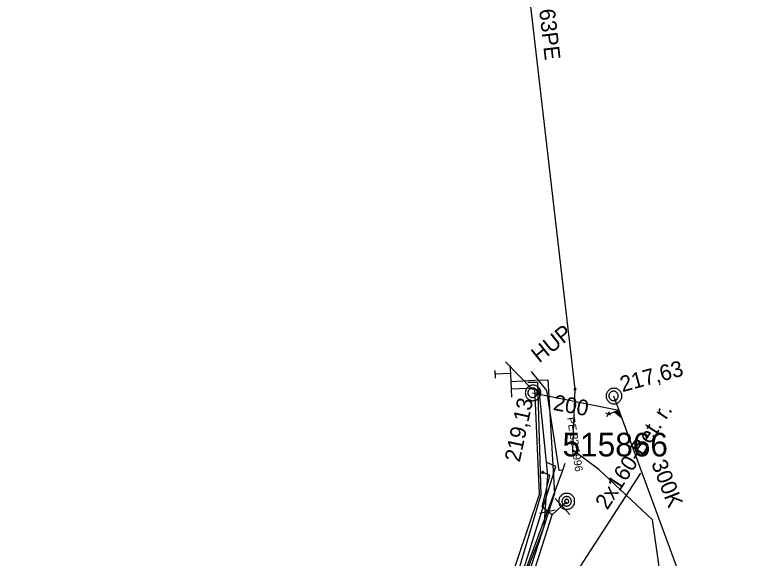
# Model space of a CAD drawing. Extents: x -746464 to -745690, y -1051581 to -1049993.
# Drawn here: x -746322.25 to -746275.6, y -1050804.49 to -1050769.98 of the extents above; entities that cross this region are included whole.
import ezdxf

# ---------------------------------------------------------------- set-up
doc = ezdxf.new("R2010")
doc.units = 0
for name, color, linetype in [('04_CETIN_sdelovaci_podzem', 7, 'Continuous'), ('45_Eltodo_popisy', 7, 'Continuous'), ('45_Eltodo_vedeni_NN_zemni', 7, 'Continuous'), ('48_Prazs_plynarenska_STL', 7, 'Continuous'), ('48_Prazs_plynarenska_STL_popisy', 7, 'Continuous'), ('51_PVaK_kanal_jednotna_neoverena poloha_pripojka', 7, 'Continuous'), ('51_PVaK_kanal_jednotna_overena poloha_rad', 7, 'Continuous'), ('51_PVaK_kanal_objekty', 7, 'Continuous'), ('51_PVaK_kanal_popisy', 7, 'Continuous'), ('51_PVaK_vodovod_chranicky_objekty', 7, 'Continuous'), ('51_PVaK_vodovod_NEPROVOZUJE PVK_neoverene poloha', 7, 'Continuous'), ('51_PVaK_vodovod_NEPROVOZUJE PVK_overena poloha', 7, 'Continuous'), ('51_PVaK_vodovod_overena poloha_pripojka', 7, 'Continuous'), ('51_PVaK_vodovod_overena poloha_rad', 7, 'Continuous'), ('51_PVaK_vodovod_popisy', 7, 'Continuous'), ('55_PREdi_NN', 7, 'Continuous'), ('55_PREdi_NN_pripojovaci_misto', 7, 'Continuous'), ('55_PREdi_stavby_popisy', 7, 'Continuous')]:
    doc.layers.add(name, color=color, linetype=linetype)

msp = doc.modelspace()

# ---------------------------------------------------------------- linework, layer by layer
at = {"layer": '04_CETIN_sdelovaci_podzem'}
for points in [[(-746289.39, -1050793.76), (-746291.09, -1050792.02)], [(-746300.25, -1050833.92), (-746294.45, -1050817.54), (-746288.63, -1050802.48), (-746288.4, -1050799.22), (-746288.94, -1050793.81), (-746289.39, -1050793.76)]]:
    msp.add_lwpolyline(points, dxfattribs=at)
at = {"layer": '45_Eltodo_vedeni_NN_zemni'}
msp.add_lwpolyline([(-746286.558, -1050816.141), (-746287.855, -1050807.461), (-746290.345, -1050806.508), (-746287.891, -1050798.664), (-746288.495, -1050798.391)], dxfattribs=at)
at = {"layer": '48_Prazs_plynarenska_STL'}
for points in [[(-746287.43, -1050798.89), (-746287.68, -1050798.92), (-746288.45, -1050793.83), (-746289.438, -1050792.627)], [(-746346.15, -1050862.68), (-746338.94, -1050859.95), (-746330.71, -1050856.43), (-746318.76, -1050851.32), (-746316.62, -1050850.41), (-746312.56, -1050848.68), (-746307.02, -1050845.98), (-746303.88, -1050842.42), (-746301.4, -1050837.35), (-746294.27, -1050817.3), (-746287.43, -1050798.89), (-746287.287, -1050798.452)]]:
    msp.add_lwpolyline(points, dxfattribs=at)
at = {"layer": '51_PVaK_kanal_jednotna_neoverena poloha_pripojka'}
msp.add_line((-746289.36, -1050793.98), (-746283.884, -1050795.09), dxfattribs=at)
at = {"layer": '51_PVaK_kanal_jednotna_overena poloha_rad'}
msp.add_lwpolyline([(-746284.22, -1050794.18), (-746283.884, -1050795.09), (-746279.35, -1050807.38)], dxfattribs=at)
at = {"layer": '51_PVaK_kanal_objekty'}
for p, q in [((-746284.388, -1050795.412), (-746284.71, -1050795.266)), ((-746284.631, -1050795.495), (-746284.481, -1050795.17))]:
    msp.add_line(p, q, dxfattribs=at)
for points in [[(-746288.83, -1050793.99), (-746288.84, -1050793.94), (-746288.84, -1050793.89), (-746288.86, -1050793.84), (-746288.88, -1050793.79), (-746288.9, -1050793.74), (-746288.93, -1050793.7), (-746288.96, -1050793.66), (-746289, -1050793.62), (-746289.04, -1050793.59), (-746289.08, -1050793.56), (-746289.13, -1050793.54), (-746289.18, -1050793.52), (-746289.23, -1050793.5), (-746289.28, -1050793.5), (-746289.33, -1050793.49), (-746289.38, -1050793.5), (-746289.43, -1050793.5), (-746289.48, -1050793.52), (-746289.53, -1050793.54), (-746289.58, -1050793.56), (-746289.62, -1050793.59), (-746289.66, -1050793.62), (-746289.7, -1050793.66), (-746289.73, -1050793.7), (-746289.76, -1050793.74), (-746289.78, -1050793.79), (-746289.8, -1050793.84), (-746289.82, -1050793.89), (-746289.82, -1050793.94), (-746289.83, -1050793.99), (-746289.82, -1050794.04), (-746289.82, -1050794.09), (-746289.8, -1050794.14), (-746289.78, -1050794.19), (-746289.76, -1050794.24), (-746289.73, -1050794.28), (-746289.7, -1050794.32), (-746289.66, -1050794.36), (-746289.62, -1050794.39), (-746289.58, -1050794.42), (-746289.53, -1050794.44), (-746289.48, -1050794.46), (-746289.43, -1050794.48), (-746289.38, -1050794.48), (-746289.33, -1050794.49), (-746289.28, -1050794.48), (-746289.23, -1050794.48), (-746289.18, -1050794.46), (-746289.13, -1050794.44), (-746289.08, -1050794.42), (-746289.04, -1050794.39), (-746289, -1050794.36), (-746288.96, -1050794.32), (-746288.93, -1050794.28), (-746288.9, -1050794.24), (-746288.88, -1050794.19), (-746288.86, -1050794.14), (-746288.84, -1050794.09), (-746288.84, -1050794.04), (-746288.83, -1050793.99)], [(-746289.06, -1050793.98), (-746289.06, -1050793.95), (-746289.066, -1050793.92), (-746289.072, -1050793.89), (-746289.084, -1050793.86), (-746289.102, -1050793.83), (-746289.12, -1050793.806), (-746289.138, -1050793.782), (-746289.162, -1050793.758), (-746289.186, -1050793.74), (-746289.21, -1050793.722), (-746289.24, -1050793.704), (-746289.27, -1050793.692), (-746289.3, -1050793.686), (-746289.33, -1050793.68), (-746289.36, -1050793.68), (-746289.39, -1050793.68), (-746289.42, -1050793.686), (-746289.45, -1050793.692), (-746289.48, -1050793.704), (-746289.51, -1050793.722), (-746289.534, -1050793.74), (-746289.558, -1050793.758), (-746289.582, -1050793.782), (-746289.6, -1050793.806), (-746289.618, -1050793.83), (-746289.636, -1050793.86), (-746289.648, -1050793.89), (-746289.654, -1050793.92), (-746289.66, -1050793.95), (-746289.66, -1050793.98), (-746289.66, -1050794.01), (-746289.654, -1050794.04), (-746289.648, -1050794.07), (-746289.636, -1050794.1), (-746289.618, -1050794.13), (-746289.6, -1050794.154), (-746289.582, -1050794.178), (-746289.558, -1050794.202), (-746289.534, -1050794.22), (-746289.51, -1050794.238), (-746289.48, -1050794.256), (-746289.45, -1050794.268), (-746289.42, -1050794.274), (-746289.39, -1050794.28), (-746289.36, -1050794.28), (-746289.33, -1050794.28), (-746289.3, -1050794.274), (-746289.27, -1050794.268), (-746289.24, -1050794.256), (-746289.21, -1050794.238), (-746289.186, -1050794.22), (-746289.162, -1050794.202), (-746289.138, -1050794.178), (-746289.12, -1050794.154), (-746289.102, -1050794.13), (-746289.084, -1050794.1), (-746289.072, -1050794.07), (-746289.066, -1050794.04), (-746289.06, -1050794.01), (-746289.06, -1050793.98)], [(-746283.69, -1050794.19), (-746283.7, -1050794.14), (-746283.7, -1050794.09), (-746283.72, -1050794.04), (-746283.74, -1050793.99), (-746283.76, -1050793.94), (-746283.79, -1050793.9), (-746283.82, -1050793.86), (-746283.86, -1050793.82), (-746283.9, -1050793.79), (-746283.94, -1050793.76), (-746283.99, -1050793.74), (-746284.04, -1050793.72), (-746284.09, -1050793.7), (-746284.14, -1050793.7), (-746284.19, -1050793.69), (-746284.24, -1050793.7), (-746284.29, -1050793.7), (-746284.34, -1050793.72), (-746284.39, -1050793.74), (-746284.44, -1050793.76), (-746284.48, -1050793.79), (-746284.52, -1050793.82), (-746284.56, -1050793.86), (-746284.59, -1050793.9), (-746284.62, -1050793.94), (-746284.64, -1050793.99), (-746284.66, -1050794.04), (-746284.68, -1050794.09), (-746284.68, -1050794.14), (-746284.69, -1050794.19), (-746284.68, -1050794.24), (-746284.68, -1050794.29), (-746284.66, -1050794.34), (-746284.64, -1050794.39), (-746284.62, -1050794.44), (-746284.59, -1050794.48), (-746284.56, -1050794.52), (-746284.52, -1050794.56), (-746284.48, -1050794.59), (-746284.44, -1050794.62), (-746284.39, -1050794.64), (-746284.34, -1050794.66), (-746284.29, -1050794.68), (-746284.24, -1050794.68), (-746284.19, -1050794.69), (-746284.14, -1050794.68), (-746284.09, -1050794.68), (-746284.04, -1050794.66), (-746283.99, -1050794.64), (-746283.94, -1050794.62), (-746283.9, -1050794.59), (-746283.86, -1050794.56), (-746283.82, -1050794.52), (-746283.79, -1050794.48), (-746283.76, -1050794.44), (-746283.74, -1050794.39), (-746283.72, -1050794.34), (-746283.7, -1050794.29), (-746283.7, -1050794.24), (-746283.69, -1050794.19)], [(-746283.92, -1050794.18), (-746283.92, -1050794.15), (-746283.926, -1050794.12), (-746283.932, -1050794.09), (-746283.944, -1050794.06), (-746283.962, -1050794.03), (-746283.98, -1050794.006), (-746283.998, -1050793.982), (-746284.022, -1050793.958), (-746284.046, -1050793.94), (-746284.07, -1050793.922), (-746284.1, -1050793.904), (-746284.13, -1050793.892), (-746284.16, -1050793.886), (-746284.19, -1050793.88), (-746284.22, -1050793.88), (-746284.25, -1050793.88), (-746284.28, -1050793.886), (-746284.31, -1050793.892), (-746284.34, -1050793.904), (-746284.37, -1050793.922), (-746284.394, -1050793.94), (-746284.418, -1050793.958), (-746284.442, -1050793.982), (-746284.46, -1050794.006), (-746284.478, -1050794.03), (-746284.496, -1050794.06), (-746284.508, -1050794.09), (-746284.514, -1050794.12), (-746284.52, -1050794.15), (-746284.52, -1050794.18), (-746284.52, -1050794.21), (-746284.514, -1050794.24), (-746284.508, -1050794.27), (-746284.496, -1050794.3), (-746284.478, -1050794.33), (-746284.46, -1050794.354), (-746284.442, -1050794.378), (-746284.418, -1050794.402), (-746284.394, -1050794.42), (-746284.37, -1050794.438), (-746284.34, -1050794.456), (-746284.31, -1050794.468), (-746284.28, -1050794.474), (-746284.25, -1050794.48), (-746284.22, -1050794.48), (-746284.19, -1050794.48), (-746284.16, -1050794.474), (-746284.13, -1050794.468), (-746284.1, -1050794.456), (-746284.07, -1050794.438), (-746284.046, -1050794.42), (-746284.022, -1050794.402), (-746283.998, -1050794.378), (-746283.98, -1050794.354), (-746283.962, -1050794.33), (-746283.944, -1050794.3), (-746283.932, -1050794.27), (-746283.926, -1050794.24), (-746283.92, -1050794.21), (-746283.92, -1050794.18)], [(-746284.556, -1050795.336), (-746283.886, -1050795.089), (-746283.71, -1050795.567), (-746284.188, -1050795.201)], [(-746284.108, -1050795.211), (-746283.913, -1050795.139), (-746283.8, -1050795.444), (-746284.109, -1050795.208)], [(-746284.025, -1050795.22), (-746283.927, -1050795.184), (-746283.87, -1050795.341), (-746284.026, -1050795.217)]]:
    msp.add_lwpolyline(points, dxfattribs=at)
at = {"layer": '51_PVaK_vodovod_chranicky_objekty'}
for p, q in [((-746286.717, -1050793.716), (-746286.697, -1050793.713)), ((-746286.606, -1050793.803), (-746286.717, -1050793.716)), ((-746286.717, -1050793.716), (-746286.714, -1050793.735)), ((-746286.705, -1050793.815), (-746286.707, -1050793.795)), ((-746286.705, -1050793.815), (-746286.617, -1050793.704)), ((-746286.705, -1050793.815), (-746286.685, -1050793.813)), ((-746286.617, -1050793.704), (-746286.637, -1050793.706)), ((-746286.606, -1050793.803), (-746286.626, -1050793.806)), ((-746286.617, -1050793.704), (-746286.615, -1050793.724)), ((-746286.606, -1050793.803), (-746286.608, -1050793.784)), ((-746288.795, -1050799.054), (-746288.663, -1050799.005)), ((-746288.795, -1050799.054), (-746288.787, -1050799.036)), ((-746288.754, -1050798.963), (-746288.762, -1050798.981)), ((-746288.754, -1050798.963), (-746288.704, -1050799.096)), ((-746288.754, -1050798.963), (-746288.736, -1050798.971)), ((-746288.663, -1050799.005), (-746288.681, -1050798.996)), ((-746288.663, -1050799.005), (-746288.671, -1050799.023)), ((-746288.795, -1050799.054), (-746288.777, -1050799.062)), ((-746288.704, -1050799.096), (-746288.723, -1050799.087)), ((-746288.704, -1050799.096), (-746288.696, -1050799.077)), ((-746287.005, -1050801.699), (-746287.923, -1050800.699)), ((-746288.93, -1050801.634), (-746287.93, -1050801.403))]:
    msp.add_line(p, q, dxfattribs=at)
for points in [[(-746286.667, -1050793.71), (-746286.672, -1050793.71), (-746286.677, -1050793.712), (-746286.682, -1050793.714), (-746286.686, -1050793.716), (-746286.691, -1050793.72), (-746286.695, -1050793.723), (-746286.698, -1050793.727), (-746286.702, -1050793.731), (-746286.704, -1050793.735), (-746286.707, -1050793.74), (-746286.709, -1050793.745), (-746286.711, -1050793.75), (-746286.711, -1050793.755), (-746286.711, -1050793.76), (-746286.711, -1050793.765), (-746286.71, -1050793.77), (-746286.709, -1050793.775), (-746286.707, -1050793.78), (-746286.705, -1050793.785), (-746286.701, -1050793.789), (-746286.698, -1050793.793), (-746286.694, -1050793.797), (-746286.69, -1050793.8), (-746286.685, -1050793.803), (-746286.681, -1050793.805), (-746286.676, -1050793.808), (-746286.671, -1050793.809), (-746286.666, -1050793.809), (-746286.66, -1050793.81), (-746286.655, -1050793.809), (-746286.65, -1050793.809), (-746286.646, -1050793.807), (-746286.641, -1050793.805), (-746286.636, -1050793.803), (-746286.631, -1050793.799), (-746286.628, -1050793.796), (-746286.624, -1050793.792), (-746286.621, -1050793.788), (-746286.618, -1050793.784), (-746286.616, -1050793.779), (-746286.613, -1050793.774), (-746286.612, -1050793.769), (-746286.611, -1050793.764), (-746286.611, -1050793.759), (-746286.612, -1050793.754), (-746286.612, -1050793.749), (-746286.614, -1050793.744), (-746286.615, -1050793.739), (-746286.618, -1050793.734), (-746286.621, -1050793.73), (-746286.625, -1050793.726), (-746286.628, -1050793.722), (-746286.633, -1050793.719), (-746286.637, -1050793.716), (-746286.641, -1050793.714), (-746286.647, -1050793.712), (-746286.652, -1050793.71), (-746286.657, -1050793.71), (-746286.662, -1050793.709), (-746286.667, -1050793.71)], [(-746288.684, -1050799.05), (-746288.682, -1050799.046), (-746288.68, -1050799.041), (-746288.679, -1050799.036), (-746288.679, -1050799.03), (-746288.68, -1050799.024), (-746288.681, -1050799.02), (-746288.682, -1050799.015), (-746288.684, -1050799.009), (-746288.686, -1050799.005), (-746288.689, -1050799.001), (-746288.692, -1050798.996), (-746288.696, -1050798.992), (-746288.7, -1050798.989), (-746288.704, -1050798.986), (-746288.708, -1050798.984), (-746288.713, -1050798.982), (-746288.718, -1050798.981), (-746288.723, -1050798.979), (-746288.728, -1050798.979), (-746288.734, -1050798.98), (-746288.739, -1050798.981), (-746288.744, -1050798.982), (-746288.749, -1050798.984), (-746288.754, -1050798.986), (-746288.758, -1050798.989), (-746288.763, -1050798.992), (-746288.767, -1050798.996), (-746288.77, -1050799), (-746288.773, -1050799.004), (-746288.775, -1050799.009), (-746288.777, -1050799.013), (-746288.778, -1050799.018), (-746288.779, -1050799.023), (-746288.779, -1050799.028), (-746288.779, -1050799.034), (-746288.778, -1050799.039), (-746288.777, -1050799.044), (-746288.775, -1050799.049), (-746288.772, -1050799.054), (-746288.77, -1050799.058), (-746288.766, -1050799.063), (-746288.763, -1050799.067), (-746288.759, -1050799.07), (-746288.754, -1050799.073), (-746288.75, -1050799.075), (-746288.745, -1050799.077), (-746288.74, -1050799.078), (-746288.735, -1050799.079), (-746288.73, -1050799.079), (-746288.724, -1050799.079), (-746288.719, -1050799.078), (-746288.715, -1050799.077), (-746288.709, -1050799.075), (-746288.705, -1050799.072), (-746288.7, -1050799.07), (-746288.696, -1050799.067), (-746288.692, -1050799.063), (-746288.689, -1050799.059), (-746288.686, -1050799.055), (-746288.684, -1050799.05)], [(-746286.694, -1050800.869), (-746286.694, -1050800.824), (-746286.694, -1050800.763), (-746286.71, -1050800.718), (-746286.725, -1050800.657), (-746286.755, -1050800.612), (-746286.785, -1050800.566), (-746286.816, -1050800.536), (-746286.861, -1050800.491), (-746286.891, -1050800.46), (-746286.937, -1050800.43), (-746286.982, -1050800.4), (-746287.043, -1050800.385), (-746287.088, -1050800.369), (-746287.149, -1050800.369), (-746287.194, -1050800.369), (-746287.255, -1050800.369), (-746287.3, -1050800.369), (-746287.346, -1050800.385), (-746287.406, -1050800.4), (-746287.452, -1050800.43), (-746287.497, -1050800.46), (-746287.528, -1050800.491), (-746287.573, -1050800.536), (-746287.603, -1050800.566), (-746287.634, -1050800.612), (-746287.664, -1050800.657), (-746287.679, -1050800.718), (-746287.694, -1050800.763), (-746287.694, -1050800.824), (-746287.694, -1050800.869), (-746287.694, -1050800.93), (-746287.694, -1050800.975), (-746287.679, -1050801.021), (-746287.664, -1050801.082), (-746287.634, -1050801.127), (-746287.603, -1050801.172), (-746287.573, -1050801.203), (-746287.528, -1050801.248), (-746287.497, -1050801.278), (-746287.452, -1050801.309), (-746287.406, -1050801.339), (-746287.346, -1050801.354), (-746287.3, -1050801.369), (-746287.255, -1050801.369), (-746287.194, -1050801.369), (-746287.149, -1050801.369), (-746287.088, -1050801.369), (-746287.043, -1050801.354), (-746286.982, -1050801.339), (-746286.937, -1050801.309), (-746286.891, -1050801.278), (-746286.861, -1050801.248), (-746286.816, -1050801.203), (-746286.785, -1050801.172), (-746286.755, -1050801.127), (-746286.725, -1050801.082), (-746286.71, -1050801.021), (-746286.694, -1050800.975), (-746286.694, -1050800.93), (-746286.694, -1050800.869)], [(-746286.891, -1050800.869), (-746286.891, -1050800.839), (-746286.906, -1050800.809), (-746286.906, -1050800.778), (-746286.922, -1050800.748), (-746286.937, -1050800.718), (-746286.952, -1050800.688), (-746286.967, -1050800.672), (-746286.997, -1050800.642), (-746287.013, -1050800.627), (-746287.043, -1050800.612), (-746287.073, -1050800.597), (-746287.103, -1050800.582), (-746287.134, -1050800.582), (-746287.164, -1050800.566), (-746287.194, -1050800.566), (-746287.225, -1050800.566), (-746287.255, -1050800.582), (-746287.285, -1050800.582), (-746287.316, -1050800.597), (-746287.346, -1050800.612), (-746287.376, -1050800.627), (-746287.391, -1050800.642), (-746287.422, -1050800.672), (-746287.437, -1050800.688), (-746287.452, -1050800.718), (-746287.467, -1050800.748), (-746287.482, -1050800.778), (-746287.482, -1050800.809), (-746287.497, -1050800.839), (-746287.497, -1050800.869), (-746287.497, -1050800.9), (-746287.482, -1050800.93), (-746287.482, -1050800.96), (-746287.467, -1050800.991), (-746287.452, -1050801.021), (-746287.437, -1050801.051), (-746287.422, -1050801.066), (-746287.391, -1050801.097), (-746287.376, -1050801.112), (-746287.346, -1050801.127), (-746287.316, -1050801.142), (-746287.285, -1050801.157), (-746287.255, -1050801.157), (-746287.225, -1050801.172), (-746287.194, -1050801.172), (-746287.164, -1050801.172), (-746287.134, -1050801.157), (-746287.103, -1050801.157), (-746287.073, -1050801.142), (-746287.043, -1050801.127), (-746287.013, -1050801.112), (-746286.997, -1050801.097), (-746286.967, -1050801.066), (-746286.952, -1050801.051), (-746286.937, -1050801.021), (-746286.922, -1050800.991), (-746286.906, -1050800.96), (-746286.906, -1050800.93), (-746286.891, -1050800.9), (-746286.891, -1050800.869)], [(-746287.058, -1050800.869), (-746287.058, -1050800.854), (-746287.073, -1050800.839), (-746287.073, -1050800.824), (-746287.073, -1050800.809), (-746287.088, -1050800.809), (-746287.088, -1050800.794), (-746287.103, -1050800.778), (-746287.119, -1050800.763), (-746287.134, -1050800.763), (-746287.134, -1050800.748), (-746287.149, -1050800.748), (-746287.164, -1050800.748), (-746287.179, -1050800.733), (-746287.194, -1050800.733), (-746287.21, -1050800.733), (-746287.225, -1050800.748), (-746287.24, -1050800.748), (-746287.255, -1050800.748), (-746287.255, -1050800.763), (-746287.27, -1050800.763), (-746287.285, -1050800.778), (-746287.3, -1050800.794), (-746287.316, -1050800.809), (-746287.316, -1050800.824), (-746287.316, -1050800.839), (-746287.331, -1050800.854), (-746287.331, -1050800.869), (-746287.331, -1050800.885), (-746287.316, -1050800.9), (-746287.316, -1050800.915), (-746287.316, -1050800.93), (-746287.3, -1050800.945), (-746287.285, -1050800.96), (-746287.27, -1050800.975), (-746287.255, -1050800.991), (-746287.24, -1050800.991), (-746287.225, -1050800.991), (-746287.21, -1050801.006), (-746287.194, -1050801.006), (-746287.179, -1050801.006), (-746287.164, -1050800.991), (-746287.149, -1050800.991), (-746287.134, -1050800.991), (-746287.119, -1050800.975), (-746287.103, -1050800.96), (-746287.088, -1050800.945), (-746287.088, -1050800.93), (-746287.073, -1050800.93), (-746287.073, -1050800.915), (-746287.073, -1050800.9), (-746287.058, -1050800.885), (-746287.058, -1050800.869)]]:
    msp.add_lwpolyline(points, dxfattribs=at)
at = {"layer": '51_PVaK_vodovod_NEPROVOZUJE PVK_neoverene poloha'}
msp.add_lwpolyline([(-746286.66, -1050793.76), (-746294.03, -1050730.166), (-746298.595, -1050712.371), (-746305.674, -1050695.977), (-746316.231, -1050682.811), (-746324.801, -1050666.789), (-746323.815, -1050649.333), (-746319.841, -1050633.435), (-746318.599, -1050621.387), (-746322.449, -1050611.948), (-746344.903, -1050590.736), (-746346.507, -1050585.236), (-746328.996, -1050535.058), (-746318.936, -1050513.695), (-746317.818, -1050494.195), (-746325.184, -1050446.994), (-746326.175, -1050412.141), (-746324.776, -1050392.335), (-746330.078, -1050363.374), (-746318.122, -1050331.887)], dxfattribs=at)
at = {"layer": '51_PVaK_vodovod_NEPROVOZUJE PVK_overena poloha'}
msp.add_lwpolyline([(-746275.698, -1050870.66), (-746275.6, -1050861.11), (-746279.61, -1050817.06), (-746281.74, -1050802.05), (-746285.15, -1050798.86), (-746286.8, -1050797.62), (-746286.66, -1050793.76)], dxfattribs=at)
at = {"layer": '51_PVaK_vodovod_overena poloha_pripojka'}
msp.add_line((-746288.11, -1050801.72), (-746288.39, -1050801.51), dxfattribs=at)
msp.add_lwpolyline([(-746288.39, -1050801.51), (-746288.75, -1050801.22), (-746288.27, -1050799.24), (-746288.73, -1050799.03)], dxfattribs=at)
at = {"layer": '51_PVaK_vodovod_overena poloha_rad'}
msp.add_line((-746287.5, -1050801.16), (-746287.21, -1050800.9), dxfattribs=at)
msp.add_lwpolyline([(-746346.29, -1050863.323), (-746337.33, -1050859.96), (-746324.926, -1050854.638), (-746321.55, -1050853.19), (-746318.51, -1050851.9), (-746304.63, -1050845.27), (-746302.59, -1050841.01), (-746298.68, -1050831.22), (-746293.24, -1050817.78), (-746288.11, -1050801.72), (-746287.5, -1050801.16)], dxfattribs=at)
at = {"layer": '55_PREdi_NN'}
for points in [[(-746290.682, -1050794.256), (-746290.705, -1050793.757), (-746290.729, -1050793.257), (-746290.752, -1050792.758), (-746290.775, -1050792.258)], [(-746290.752, -1050792.758), (-746291.251, -1050792.781)], [(-746290.729, -1050793.257), (-746289.249, -1050793.188), (-746288.398, -1050793.165), (-746287.974, -1050800.368), (-746289.857, -1050806.206), (-746286.467, -1050807.807), (-746282.228, -1050839.071), (-746283.077, -1050842.109), (-746279.169, -1050871.142)], [(-746289.656, -1050793.306), (-746289.043, -1050793.3), (-746288.827, -1050800.454), (-746290.676, -1050806.684)], [(-746291.392, -1050807.681), (-746291.047, -1050806.699), (-746288.916, -1050800.416), (-746289.225, -1050793.688), (-746290.705, -1050793.757)]]:
    msp.add_lwpolyline(points, dxfattribs=at)
at = {"layer": '55_PREdi_NN_pripojovaci_misto'}
for p, q in [((-746291.763, -1050792.558), (-746291.737, -1050793.057)), ((-746291.251, -1050792.781), (-746291.75, -1050792.807))]:
    msp.add_line(p, q, dxfattribs=at)
at = {"layer": '55_PREdi_stavby_popisy'}
msp.add_lwpolyline([(-746288.004, -1050807.637), (-746285.926, -1050804.384), (-746282.479, -1050799.093)], dxfattribs=at)

# ---------------------------------------------------------------- texts
at = {"layer": '45_Eltodo_popisy'}
msp.add_text('515866', height=1.5, dxfattribs=at).set_placement((-746287.46, -1050798.023))
at = {"layer": '48_Prazs_plynarenska_STL_popisy'}
for s, height, rotation, p in [('HUP', 1, 39, (-746288.938, -1050792.127)), ('PE 32 1996', 0.5, 278.6023, (-746287.176, -1050795.563))]:
    msp.add_text(s, height=height, rotation=rotation, dxfattribs=at).set_placement(p)
at = {"layer": '51_PVaK_kanal_popisy'}
for s, rotation, p in [('217,63', 15.2785, (-746283.656, -1050793.948)), ('219,13', 77.8206, (-746290.18, -1050798.428)), ('200', 349.541, (-746288.102, -1050795.066)), ('300K', 291.2502, (-746281.842, -1050798.45))]:
    msp.add_text(s, height=1, rotation=rotation, dxfattribs=at).set_placement(p)
at = {"layer": '51_PVaK_vodovod_popisy'}
msp.add_text('63PE', height=1, rotation=276.6095, dxfattribs=at).set_placement((-746288.95, -1050769.661))
at = {"layer": '55_PREdi_stavby_popisy'}
msp.add_text('2x160-Bet. r.', height=1, rotation=56.9157, dxfattribs=at).set_placement((-746284.621, -1050801.465))

doc.saveas('drawing.dxf')
